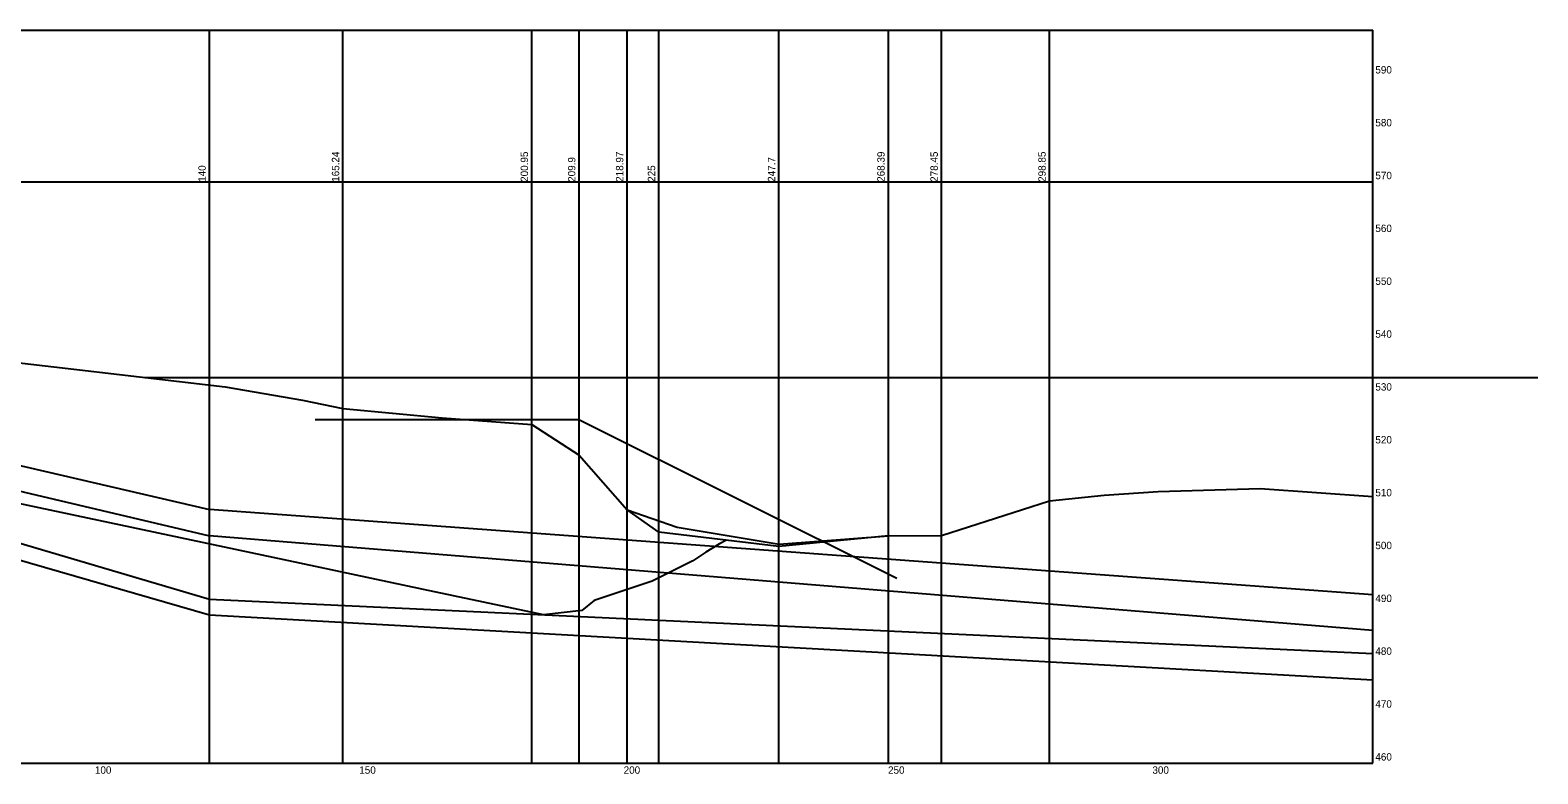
# Model space of a CAD drawing. Extents: x -64 to 1064, y -32 to 640.
# Drawn here: x 86.1 to 371.2, y 458 to 598.7 of the extents above; entities that cross this region are included whole.
import ezdxf

# ---------------------------------------------------------------- set-up
doc = ezdxf.new("R2010")
doc.units = 0
for name, color, linetype in [('GT_Project_Soil_Layers', 7, 'Continuous'), ('GT_X_Shear_Surface', 7, 'Continuous'), ('SC_Scratch1', 7, 'Continuous'), ('SH_Major_Grid_Line', 7, 'Continuous'), ('SH_Text', 7, 'Continuous')]:
    doc.layers.add(name, color=color, linetype=linetype)

msp = doc.modelspace()

# ---------------------------------------------------------------- linework, layer by layer
at = {"layer": 'GT_Project_Soil_Layers'}
for p, q in [((340, 491.84), (120, 508)), ((340, 485.1), (120, 503)), ((340, 480.69), (120, 491)), ((340, 475.69), (120, 488))]:
    msp.add_line(p, q, dxfattribs=at)
for points in [[(-60, 546.61), (8.1, 532.8), (35.3, 527.7), (120, 508)], [(-60, 541.07), (8.1, 525), (35.3, 523), (120, 503)], [(120, 491), (35.3, 516), (8.1, 521.8), (-60, 539.88)], [(120, 488), (35.3, 512.5), (8.1, 518.2), (-60, 536.8)]]:
    msp.add_lwpolyline(points, dxfattribs=at)
at = {"layer": 'GT_X_Shear_Surface'}
msp.add_lwpolyline([(217.77, 502.18), (216.44, 501.53), (213.9, 499.94), (211.4, 498.28), (203.7, 494.41), (192.74, 490.77), (190.4, 488.89), (183.2, 488.04), (160.5, 492.86), (134.1, 498.46), (39.3, 518.57), (20.9, 522.48), (9.49, 524.9), (-0.43, 527), (-6.78, 535.89), (-9.49, 544.63), (-15.48, 556.27)], dxfattribs=at)
at = {"layer": 'SC_Scratch1'}
for p, q in [((107.79, 533), (371.23, 533)), ((190, 525), (140, 525)), ((190, 525), (250, 495))]:
    msp.add_line(p, q, dxfattribs=at)
for points in [[(66.55, 537.77), (90.59, 535), (122.96, 531.23), (137.6, 528.71), (145.24, 527.13), (164, 525.37), (180.94, 524.1), (189.9, 518.28), (198.97, 507.96), (208.46, 504.68), (227.74, 501.45), (248.39, 503.01), (258.45, 503.07), (278.85, 509.66), (289.2, 510.72), (299.44, 511.4), (318.74, 512), (340, 510.45)], [(248.39, 503.01), (227.7, 501), (205, 503.7), (198.97, 507.96)]]:
    msp.add_lwpolyline(points, dxfattribs=at)
at = {"layer": 'SH_Major_Grid_Line'}
for p, q in [((-60, 598.71), (340, 598.71)), ((120, 460), (120, 598.71)), ((145.24, 460), (145.24, 598.71)), ((180.95, 460), (180.95, 598.71)), ((189.9, 460), (189.9, 598.71)), ((198.97, 460), (198.97, 598.71)), ((205, 460), (205, 598.71)), ((227.7, 460), (227.7, 598.71)), ((248.39, 460), (248.39, 598.71)), ((258.45, 460), (258.45, 598.71)), ((278.85, 460), (278.85, 598.71)), ((340, 460), (340, 598.71)), ((-60, 570), (340, 570)), ((-60, 460), (340, 460))]:
    msp.add_line(p, q, dxfattribs=at)

# ---------------------------------------------------------------- texts
at = {"layer": 'GT_Project_Soil_Layers'}
for s, p in [('165.24', (144.54, 570)), ('200.95', (180.25, 570)), ('209.9', (189.2, 570)), ('218.97', (198.27, 570)), ('247.7', (227, 570)), ('268.39', (247.69, 570)), ('278.45', (257.75, 570)), ('298.85', (278.15, 570)), ('140', (119.3, 570)), ('225', (204.3, 570))]:
    msp.add_text(s, height=1.4, rotation=90, dxfattribs=at).set_placement(p)
at = {"layer": 'SH_Text'}
for s, p in [('590', (340.5, 590.5)), ('580', (340.5, 580.5)), ('570', (340.5, 570.5)), ('560', (340.5, 560.5)), ('550', (340.5, 550.5)), ('540', (340.5, 540.5)), ('530', (340.5, 530.5)), ('520', (340.5, 520.5)), ('510', (340.5, 510.5)), ('500', (340.5, 500.5)), ('490', (340.5, 490.5)), ('480', (340.5, 480.5)), ('470', (340.5, 470.5)), ('100', (98.33, 458)), ('150', (148.33, 458)), ('200', (198.33, 458)), ('250', (248.33, 458)), ('300', (298.33, 458)), ('460', (340.5, 460.5))]:
    msp.add_text(s, height=1.4, dxfattribs=at).set_placement(p)

doc.saveas('drawing.dxf')
